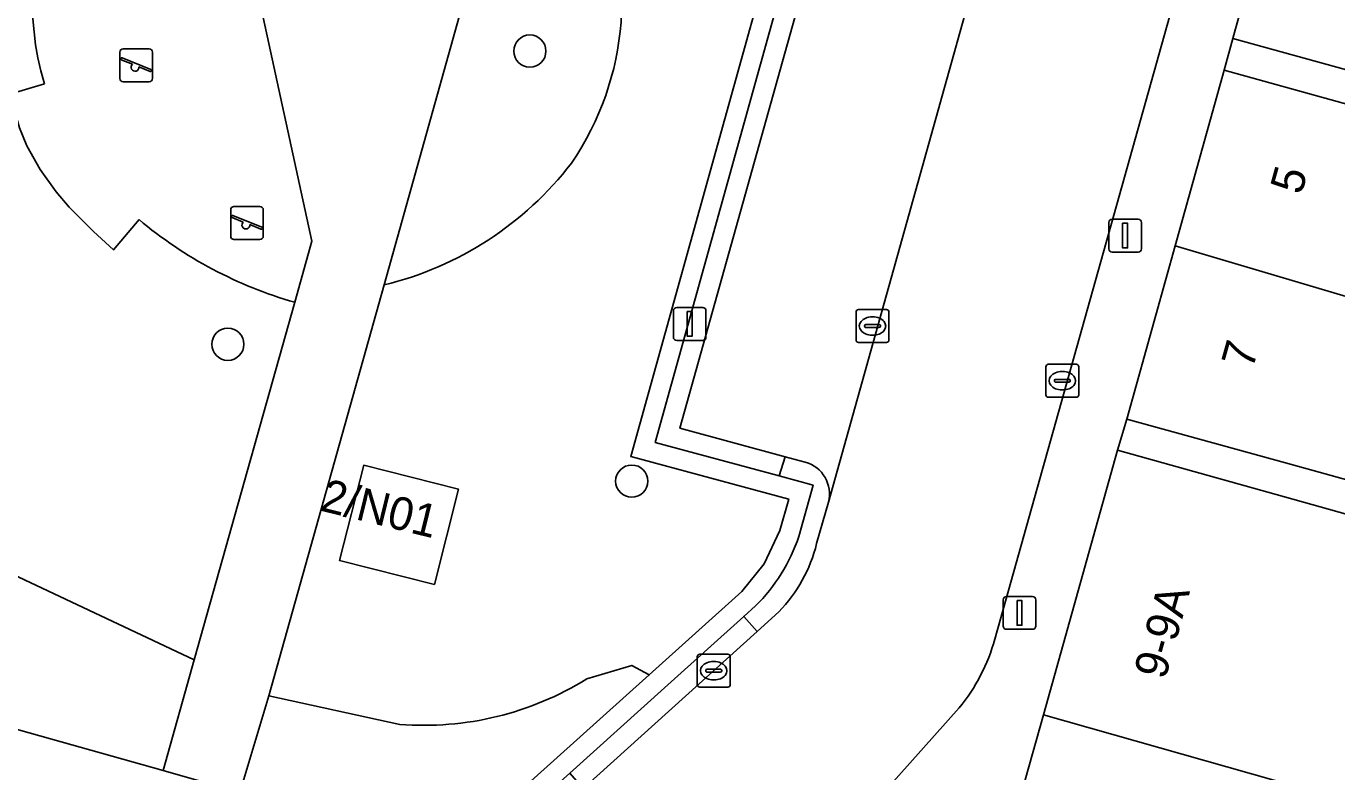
# Model space of a CAD drawing. Extents: x 158086 to 159499, y 382904 to 383981.
# Drawn here: x 158689.97 to 158729.8, y 383283.29 to 383305.96 of the extents above; entities that cross this region are included whole.
import ezdxf

# ---------------------------------------------------------------- set-up
doc = ezdxf.new("R2010")
doc.units = 0
for name, color, linetype in [('IMGEO_Boom', 7, 'Continuous'), ('IMGEO_Erf', 7, 'Continuous'), ('IMGEO_Groenvoorziening', 7, 'Continuous'), ('IMGEO_Haag', 7, 'Continuous'), ('IMGEO_Kolk', 7, 'Continuous'), ('IMGEO_Lichtmast', 7, 'Continuous'), ('IMGEO_Pand', 7, 'Continuous'), ('IMGEO_Pand_nummerreeks', 7, 'Continuous'), ('IMGEO_Parkeervlak_open', 7, 'Continuous'), ('IMGEO_Rijbaan_lokaal_open', 7, 'Continuous'), ('IMGEO_Speelvoorziening', 7, 'Continuous'), ('IMGEO_Terreindeel_zand', 7, 'Continuous'), ('IMGEO_Voetpad_open', 7, 'Continuous')]:
    doc.layers.add(name, color=color, linetype=linetype)

msp = doc.modelspace()

# ---------------------------------------------------------------- linework, layer by layer
at = {"layer": 'IMGEO_Boom'}
for centre in [(158705.278, 383305.204), (158696.102, 383296.29), (158708.374, 383292.129)]:
    msp.add_circle(centre, 0.489, dxfattribs=at)
at = {"layer": 'IMGEO_Erf'}
for points in [[(158750.621, 383298.706), (158746.826, 383299.786), (158746.884, 383299.995), (158740.051, 383301.883), (158726.638, 383305.589), (158726.38, 383304.619), (158731.2, 383303.287), (158735.174, 383302.189), (158737.677, 383301.497), (158736.955, 383298.883), (158739.334, 383298.209), (158739.21, 383297.772), (158742.082, 383296.958), (158741.87, 383296.21), (158745.171, 383295.274), (158744.648, 383293.427), (158746.73, 383292.809), (158748.777, 383292.201), (158750.043, 383296.667)], [(158723.419, 383294.014), (158723.139, 383293.069), (158727.954, 383291.719), (158737.135, 383289.145), (158747.117, 383286.346), (158748.21, 383290.202), (158746.156, 383290.784), (158746.068, 383290.474), (158737.806, 383292.815), (158732.961, 383294.188), (158732.222, 383291.582), (158728.239, 383292.682)]]:
    msp.add_lwpolyline(points, close=True, dxfattribs=at)
at = {"layer": 'IMGEO_Groenvoorziening'}
for points in [[(158715.651, 383319.137), (158708.346, 383292.883), (158713.145, 383291.584), (158712.877, 383290.631), (158712.4, 383289.615), (158711.72, 383288.771), (158708.905, 383286.24), (158705.305, 383283.005), (158704.465, 383281.869), (158703.916, 383280.587), (158704.499, 383280.425), (158704.989, 383281.568), (158705.749, 383282.597), (158706.491, 383283.248), (158709.467, 383285.933)], [(158707.006, 383286.118), (158708.372, 383286.529), (158708.905, 383286.24), (158711.72, 383288.771), (158712.4, 383289.615), (158712.877, 383290.631), (158713.145, 383291.584), (158708.346, 383292.883), (158715.651, 383319.137)], [(158713.449, 383290.447), (158713.886, 383292.005), (158712.858, 383292.286), (158709.086, 383293.304), (158715.763, 383317.299), (158716.138, 383318.648)], [(158707.225, 383310.544), (158703.141, 383306.283), (158700.848, 383298.094)], [(158693.401, 383300.083), (158692.625, 383299.161), (158692.016, 383299.717), (158691.282, 383300.454), (158690.88, 383300.925), (158690.395, 383301.603), (158689.993, 383302.328), (158689.768, 383302.869), (158689.475, 383303.894), (158690.525, 383304.204)], [(158700.848, 383298.094), (158697.345, 383285.602), (158701.326, 383284.735)], [(158687.958, 383290.048), (158695.081, 383286.692), (158698.135, 383297.568)], [(158684.98, 383293.485), (158683.014, 383286.461), (158683.206, 383286.407), (158694.138, 383283.337), (158695.081, 383286.692), (158687.958, 383290.048)], [(158709.467, 383285.933), (158711.776, 383288.016), (158712.136, 383288.337)], [(158701.326, 383284.735), (158697.345, 383285.602), (158696.463, 383282.664), (158703.916, 383280.587), (158704.465, 383281.869), (158705.305, 383283.005), (158708.905, 383286.24), (158708.372, 383286.529), (158707.006, 383286.118)]]:
    msp.add_lwpolyline(points, dxfattribs=at)
msp.add_lwpolyline([(158702.377, 383288.983), (158699.495, 383289.712), (158700.229, 383292.611), (158703.111, 383291.882)], close=True, dxfattribs=at)
for centre, radius, start, end in [((158698.909, 383306.684), 8.744, 114.0649, 196.48), ((158699.264, 383306.766), 8.812, 325.6717, 25.3856), ((158699.264, 383306.766), 8.812, 325.6717, 25.3856), ((158698.436, 383308.029), 10.224, 283.6433, 322.4405), ((158698.436, 383308.029), 10.224, 283.6433, 322.4405), ((158701.631, 383309.861), 12.781, 229.9142, 254.1257), ((158708.419, 383292.113), 5.298, 314.5439, 341.6702), ((158702.056, 383294.094), 9.388, 265.5431, 301.8258), ((158702.056, 383294.094), 9.388, 265.5431, 301.8258)]:
    msp.add_arc(centre, radius, start, end, dxfattribs=at)
at = {"layer": 'IMGEO_Haag'}
for points in [[(158715.651, 383319.137), (158708.346, 383292.883), (158713.145, 383291.584), (158712.877, 383290.631), (158712.4, 383289.615), (158711.72, 383288.771), (158708.905, 383286.24), (158705.305, 383283.005), (158704.465, 383281.869), (158703.916, 383280.587), (158704.499, 383280.425), (158704.989, 383281.568), (158705.749, 383282.597), (158706.491, 383283.248), (158709.467, 383285.933)], [(158713.449, 383290.447), (158713.886, 383292.005), (158712.858, 383292.286), (158709.086, 383293.304), (158715.763, 383317.299), (158716.138, 383318.648)], [(158709.467, 383285.933), (158711.776, 383288.016), (158712.136, 383288.337)]]:
    msp.add_lwpolyline(points, dxfattribs=at)
msp.add_arc((158708.419, 383292.113), 5.298, 314.5439, 341.6702, dxfattribs=at)
at = {"layer": 'IMGEO_Kolk'}
for p, q in [((158715.265, 383297.344), (158716.117, 383297.344)), ((158715.19, 383296.418), (158715.19, 383297.27)), ((158715.678, 383297.124), (158715.703, 383297.124)), ((158716.191, 383297.27), (158716.191, 383296.418)), ((158715.449, 383296.838), (158715.449, 383296.85)), ((158715.887, 383296.801), (158715.489, 383296.801)), ((158715.492, 383296.887), (158715.89, 383296.887)), ((158715.701, 383296.564), (158715.676, 383296.564)), ((158715.933, 383296.85), (158715.933, 383296.838)), ((158716.117, 383296.344), (158715.265, 383296.344)), ((158720.958, 383294.755), (158720.958, 383295.607)), ((158721.033, 383295.681), (158721.885, 383295.681)), ((158721.446, 383295.461), (158721.471, 383295.461)), ((158721.959, 383295.607), (158721.959, 383294.755)), ((158721.217, 383295.175), (158721.217, 383295.187)), ((158721.655, 383295.138), (158721.257, 383295.138)), ((158721.26, 383295.224), (158721.658, 383295.224)), ((158721.701, 383295.187), (158721.701, 383295.175)), ((158721.885, 383294.681), (158721.033, 383294.681)), ((158721.469, 383294.901), (158721.444, 383294.901)), ((158710.365, 383285.94), (158710.365, 383286.792)), ((158710.44, 383286.866), (158711.292, 383286.866)), ((158710.853, 383286.646), (158710.878, 383286.646)), ((158711.366, 383286.792), (158711.366, 383285.94)), ((158710.624, 383286.36), (158710.624, 383286.372)), ((158711.062, 383286.323), (158710.664, 383286.323)), ((158710.667, 383286.409), (158711.065, 383286.409)), ((158711.108, 383286.372), (158711.108, 383286.36)), ((158711.292, 383285.866), (158710.44, 383285.866)), ((158710.876, 383286.086), (158710.851, 383286.086))]:
    msp.add_line(p, q, dxfattribs=at)
for points in [[(158715.265, 383297.344), (158716.117, 383297.344)], [(158715.19, 383296.418), (158715.19, 383297.27)], [(158716.191, 383297.27), (158716.191, 383296.418)], [(158716.117, 383296.344), (158715.265, 383296.344)], [(158720.958, 383294.755), (158720.958, 383295.607)], [(158721.033, 383295.681), (158721.885, 383295.681)], [(158721.959, 383295.607), (158721.959, 383294.755)], [(158721.885, 383294.681), (158721.033, 383294.681)], [(158710.365, 383285.94), (158710.365, 383286.792)], [(158710.44, 383286.866), (158711.292, 383286.866)], [(158711.366, 383286.792), (158711.366, 383285.94)], [(158711.292, 383285.866), (158710.44, 383285.866)]]:
    msp.add_lwpolyline(points, dxfattribs=at)
for centre, radius, start, end in [((158715.267, 383297.268), 0.0765, 91.552, 178.448), ((158715.267, 383297.268), 0.0765, 91.552, 178.448), ((158716.115, 383297.268), 0.0765, 1.552, 88.448), ((158716.115, 383297.268), 0.0765, 1.552, 88.448), ((158715.489, 383296.847), 0.0403, 85.8775, 175.7526), ((158715.486, 383296.837), 0.0366, 178.938, 274.7102), ((158715.89, 383296.844), 0.043, 264.8664, 352.4533), ((158715.894, 383296.849), 0.0386, 1.7309, 96.639), ((158715.267, 383296.42), 0.0765, 181.552, 268.448), ((158715.267, 383296.42), 0.0765, 181.552, 268.448), ((158716.115, 383296.42), 0.0765, 271.552, 358.448), ((158716.115, 383296.42), 0.0765, 271.552, 358.448), ((158721.035, 383295.605), 0.0765, 91.552, 178.448), ((158721.035, 383295.605), 0.0765, 91.552, 178.448), ((158721.883, 383295.605), 0.0765, 1.552, 88.448), ((158721.883, 383295.605), 0.0765, 1.552, 88.448), ((158721.257, 383295.184), 0.0403, 85.8775, 175.7526), ((158721.254, 383295.174), 0.0366, 178.938, 274.7102), ((158721.658, 383295.181), 0.043, 264.8664, 352.4533), ((158721.662, 383295.186), 0.0386, 1.7309, 96.639), ((158721.035, 383294.757), 0.0765, 181.552, 268.448), ((158721.035, 383294.757), 0.0765, 181.552, 268.448), ((158721.883, 383294.757), 0.0765, 271.552, 358.448), ((158721.883, 383294.757), 0.0765, 271.552, 358.448), ((158710.442, 383286.79), 0.0765, 91.552, 178.448), ((158710.442, 383286.79), 0.0765, 91.552, 178.448), ((158711.29, 383286.79), 0.0765, 1.552, 88.448), ((158711.29, 383286.79), 0.0765, 1.552, 88.448), ((158710.664, 383286.369), 0.0403, 85.8775, 175.7526), ((158710.661, 383286.359), 0.0366, 178.938, 274.7102), ((158711.065, 383286.366), 0.043, 264.8664, 352.4533), ((158711.069, 383286.371), 0.0386, 1.7309, 96.639), ((158710.442, 383285.942), 0.0765, 181.552, 268.448), ((158710.442, 383285.942), 0.0765, 181.552, 268.448), ((158711.29, 383285.942), 0.0765, 271.552, 358.448), ((158711.29, 383285.942), 0.0765, 271.552, 358.448)]:
    msp.add_arc(centre, radius, start, end, dxfattribs=at)
for centre, major_axis, ratio, start_param, end_param in [((158715.677, 383296.844), (-0.387, 0.002), 0.722429, 4.712389, 7.853982), ((158715.702, 383296.844), (-0.39, 0.002), 0.717154, 1.570796, 4.712389), ((158721.445, 383295.181), (-0.387, 0.002), 0.722429, 4.712389, 7.853982), ((158721.47, 383295.181), (-0.39, 0.002), 0.717154, 1.570796, 4.712389), ((158710.852, 383286.366), (-0.387, 0.002), 0.722429, 4.712389, 7.853982), ((158710.877, 383286.366), (-0.39, 0.002), 0.717154, 1.570796, 4.712389)]:
    msp.add_ellipse(centre, major_axis=major_axis, ratio=ratio, start_param=start_param, end_param=end_param, dxfattribs=at)
at = {"layer": 'IMGEO_Lichtmast'}
for p, q in [((158722.972, 383300.094), (158723.762, 383300.094)), ((158723.762, 383300.094), (158722.972, 383300.094)), ((158722.872, 383299.194), (158722.872, 383299.994)), ((158722.872, 383299.994), (158722.872, 383299.194)), ((158723.862, 383299.994), (158723.862, 383299.194)), ((158723.862, 383299.194), (158723.862, 383299.994)), ((158723.762, 383299.094), (158722.972, 383299.094)), ((158722.972, 383299.094), (158723.762, 383299.094)), ((158709.64, 383296.507), (158709.64, 383297.307)), ((158709.64, 383297.307), (158709.64, 383296.507)), ((158709.74, 383297.407), (158710.53, 383297.407)), ((158710.53, 383297.407), (158709.74, 383297.407)), ((158710.63, 383297.307), (158710.63, 383296.507)), ((158710.63, 383296.507), (158710.63, 383297.307)), ((158710.53, 383296.407), (158709.74, 383296.407)), ((158709.74, 383296.407), (158710.53, 383296.407)), ((158719.763, 383288.624), (158720.553, 383288.624)), ((158720.553, 383288.624), (158719.763, 383288.624)), ((158719.663, 383287.724), (158719.663, 383288.524)), ((158719.663, 383288.524), (158719.663, 383287.724)), ((158720.653, 383288.524), (158720.653, 383287.724)), ((158720.653, 383287.724), (158720.653, 383288.524)), ((158720.553, 383287.624), (158719.763, 383287.624)), ((158719.763, 383287.624), (158720.553, 383287.624))]:
    msp.add_line(p, q, dxfattribs=at)
for points in [[(158723.292, 383299.969), (158723.442, 383299.969), (158723.442, 383299.219), (158723.292, 383299.219), (158723.292, 383299.969)], [(158710.06, 383297.282), (158710.21, 383297.282), (158710.21, 383296.532), (158710.06, 383296.532), (158710.06, 383297.282)], [(158720.083, 383288.499), (158720.233, 383288.499), (158720.233, 383287.749), (158720.083, 383287.749), (158720.083, 383288.499)]]:
    msp.add_lwpolyline(points, dxfattribs=at)
for centre, start, end in [((158722.972, 383299.994), 90, 180), ((158722.972, 383299.994), 90, 180), ((158723.762, 383299.994), 0, 90), ((158723.762, 383299.994), 360, 90), ((158722.972, 383299.194), 180, 270), ((158722.972, 383299.194), 180, 270), ((158723.762, 383299.194), 270, 0), ((158723.762, 383299.194), 270, 0), ((158709.74, 383297.307), 90, 180), ((158709.74, 383297.307), 90, 180), ((158710.53, 383297.307), 0, 90), ((158710.53, 383297.307), 360, 90), ((158709.74, 383296.507), 180, 270), ((158709.74, 383296.507), 180, 270), ((158710.53, 383296.507), 270, 0), ((158710.53, 383296.507), 270, 0), ((158719.763, 383288.524), 90, 180), ((158719.763, 383288.524), 90, 180), ((158720.553, 383288.524), 0, 90), ((158720.553, 383288.524), 360, 90), ((158719.763, 383287.724), 180, 270), ((158719.763, 383287.724), 180, 270), ((158720.553, 383287.724), 270, 0), ((158720.553, 383287.724), 270, 0)]:
    msp.add_arc(centre, 0.1, start, end, dxfattribs=at)
at = {"layer": 'IMGEO_Pand'}
for points in [[(158734.063, 383310.168), (158729.552, 383311.413), (158728.013, 383310.572), (158726.638, 383305.589), (158740.051, 383301.883), (158746.884, 383299.995), (158746.826, 383299.786), (158750.621, 383298.706), (158752.515, 383305.385), (158748.706, 383306.463), (158747.639, 383302.691), (158742.1, 383304.249), (158743.079, 383307.796), (158742.083, 383309.564), (158738.149, 383310.65), (158736.503, 383309.495), (158734.326, 383310.095)], [(158726.38, 383304.619), (158724.891, 383299.284), (158744.648, 383293.427), (158745.171, 383295.274), (158741.87, 383296.21), (158742.082, 383296.958), (158739.21, 383297.772), (158739.334, 383298.209), (158736.955, 383298.883), (158737.677, 383301.497), (158735.174, 383302.189), (158731.2, 383303.287)], [(158724.891, 383299.284), (158723.419, 383294.014), (158728.239, 383292.682), (158732.222, 383291.582), (158732.961, 383294.188), (158737.806, 383292.815), (158746.068, 383290.474), (158746.156, 383290.784), (158748.21, 383290.202), (158748.777, 383292.201), (158746.73, 383292.809), (158744.648, 383293.427)], [(158747.117, 383286.346), (158737.135, 383289.145), (158727.954, 383291.719), (158723.139, 383293.069), (158720.882, 383285.022), (158729.99, 383282.438), (158730.021, 383282.546), (158734.867, 383281.172), (158742.063, 383279.133), (158745.03, 383278.292), (158745.391, 383279.615), (158745.223, 383279.663)], [(158702.377, 383288.983), (158703.111, 383291.882), (158700.229, 383292.611), (158699.495, 383289.712)], [(158734.867, 383281.172), (158730.021, 383282.546), (158729.99, 383282.438), (158720.882, 383285.022), (158719.351, 383279.567), (158724.166, 383278.217), (158733.304, 383275.655), (158734.145, 383278.623)]]:
    msp.add_lwpolyline(points, close=True, dxfattribs=at)
at = {"layer": 'IMGEO_Parkeervlak_open'}
for points in [[(158720.628, 383315.931), (158716.38, 383317.125), (158709.84, 383293.736), (158713.041, 383292.873), (158713.646, 383292.709)], [(158714.354, 383291.491), (158721.142, 383315.77), (158721.255, 383316.174)]]:
    msp.add_lwpolyline(points, dxfattribs=at)
msp.add_arc((158713.373, 383291.736), 1.011, 345.9856, 74.3516, dxfattribs=at)
at = {"layer": 'IMGEO_Rijbaan_lokaal_open'}
for points in [[(158726.409, 383312.281), (158726.934, 383314.154), (158721.142, 383315.77), (158714.354, 383291.491), (158713.992, 383290.23)], [(158719.408, 383287.329), (158726.409, 383312.281)], [(158712.839, 383288.156), (158712.19, 383287.558), (158706.901, 383282.787), (158706, 383281.923), (158713.492, 383279.816), (158718.325, 383285.237)]]:
    msp.add_lwpolyline(points, dxfattribs=at)
for centre, radius, start, end in [((158709.636, 383291.294), 4.484, 315.5852, 346.2728), ((158713.967, 383288.819), 5.641, 320.5783, 344.6818)]:
    msp.add_arc(centre, radius, start, end, dxfattribs=at)
at = {"layer": 'IMGEO_Speelvoorziening'}
for p, q in [((158692.918, 383305.273), (158693.708, 383305.273)), ((158693.708, 383305.273), (158692.918, 383305.273)), ((158692.818, 383304.373), (158692.818, 383305.173)), ((158692.818, 383305.173), (158692.818, 383304.373)), ((158693.201, 383304.801), (158692.862, 383304.938)), ((158692.887, 383304.998), (158693.763, 383304.645)), ((158693.808, 383305.173), (158693.808, 383304.373)), ((158693.808, 383304.373), (158693.808, 383305.173)), ((158693.739, 383304.585), (158693.399, 383304.722)), ((158693.708, 383304.273), (158692.918, 383304.273)), ((158692.918, 383304.273), (158693.708, 383304.273)), ((158696.187, 383299.578), (158696.187, 383300.378)), ((158696.187, 383300.378), (158696.187, 383299.578)), ((158696.57, 383300.006), (158696.231, 383300.143)), ((158696.256, 383300.203), (158697.132, 383299.85)), ((158696.287, 383300.478), (158697.077, 383300.478)), ((158697.077, 383300.478), (158696.287, 383300.478)), ((158697.177, 383300.378), (158697.177, 383299.578)), ((158697.177, 383299.578), (158697.177, 383300.378)), ((158697.108, 383299.79), (158696.768, 383299.927)), ((158697.077, 383299.478), (158696.287, 383299.478)), ((158696.287, 383299.478), (158697.077, 383299.478))]:
    msp.add_line(p, q, dxfattribs=at)
for centre, radius, start, end in [((158692.918, 383305.173), 0.1, 90, 180), ((158692.918, 383305.173), 0.1, 90, 180), ((158693.708, 383305.173), 0.1, 0, 90), ((158693.708, 383305.173), 0.1, 360, 90), ((158692.875, 383304.968), 0.0327, 68.078, 248.078), ((158693.28, 383304.711), 0.12, 130.9928, 5.1632), ((158693.751, 383304.615), 0.0327, 248.078, 68.078), ((158692.918, 383304.373), 0.1, 180, 270), ((158692.918, 383304.373), 0.1, 180, 270), ((158693.708, 383304.373), 0.1, 270, 0), ((158693.708, 383304.373), 0.1, 270, 0), ((158696.287, 383300.378), 0.1, 90, 180), ((158696.287, 383300.378), 0.1, 90, 180), ((158696.244, 383300.173), 0.0327, 68.078, 248.078), ((158697.077, 383300.378), 0.1, 0, 90), ((158697.077, 383300.378), 0.1, 360, 90), ((158696.649, 383299.916), 0.12, 130.9928, 5.1632), ((158697.12, 383299.82), 0.0327, 248.078, 68.078), ((158696.287, 383299.578), 0.1, 180, 270), ((158696.287, 383299.578), 0.1, 180, 270), ((158697.077, 383299.578), 0.1, 270, 0), ((158697.077, 383299.578), 0.1, 270, 0)]:
    msp.add_arc(centre, radius, start, end, dxfattribs=at)
at = {"layer": 'IMGEO_Terreindeel_zand'}
for points in [[(158698.135, 383297.568), (158698.657, 383299.429), (158695.344, 383314.668)], [(158690.525, 383304.204), (158689.475, 383303.894), (158689.768, 383302.869), (158689.993, 383302.328), (158690.395, 383301.603), (158690.88, 383300.925), (158691.282, 383300.454), (158692.016, 383299.717), (158692.625, 383299.161), (158693.401, 383300.083)]]:
    msp.add_lwpolyline(points, dxfattribs=at)
for centre, radius, start, end in [((158698.909, 383306.684), 8.744, 114.0649, 196.48), ((158701.631, 383309.861), 12.781, 229.9142, 254.1257)]:
    msp.add_arc(centre, radius, start, end, dxfattribs=at)
at = {"layer": 'IMGEO_Voetpad_open'}
for points in [[(158693.404, 383323.589), (158695.344, 383314.668), (158698.657, 383299.429), (158698.135, 383297.568), (158695.081, 383286.692), (158694.138, 383283.337), (158696.463, 383282.664), (158697.345, 383285.602), (158700.848, 383298.094), (158703.141, 383306.283)], [(158712.681, 383278.089), (158705.06, 383280.231), (158704.499, 383280.425), (158703.916, 383280.587), (158696.463, 383282.664), (158694.138, 383283.337), (158683.206, 383286.407), (158683.014, 383286.461), (158682.436, 383286.623), (158684.564, 383294.149), (158692.698, 383323.292)], [(158713.33, 383257.83), (158715.488, 383265.62), (158717.6, 383273.245), (158718.49, 383276.457), (158719.072, 383278.559), (158719.351, 383279.567), (158720.882, 383285.022), (158723.139, 383293.069), (158723.419, 383294.014), (158724.891, 383299.284), (158726.38, 383304.619), (158726.638, 383305.589), (158728.013, 383310.572), (158729.552, 383311.413), (158726.409, 383312.281), (158719.408, 383287.329)], [(158713.646, 383292.709), (158713.041, 383292.873), (158712.858, 383292.286), (158713.886, 383292.005), (158713.449, 383290.447)], [(158713.992, 383290.23), (158714.354, 383291.491)], [(158712.136, 383288.337), (158711.776, 383288.016), (158712.19, 383287.558), (158712.839, 383288.156)], [(158718.325, 383285.237), (158713.492, 383279.816)]]:
    msp.add_lwpolyline(points, dxfattribs=at)
for points in [[(158716.38, 383317.125), (158715.763, 383317.299), (158709.086, 383293.304), (158712.858, 383292.286), (158713.041, 383292.873), (158709.84, 383293.736)], [(158706.491, 383283.248), (158706.901, 383282.787), (158712.19, 383287.558), (158711.776, 383288.016), (158709.467, 383285.933)]]:
    msp.add_lwpolyline(points, close=True, dxfattribs=at)
for centre, radius, start, end in [((158713.373, 383291.736), 1.011, 345.9856, 74.3516), ((158708.419, 383292.113), 5.298, 314.5439, 341.6702), ((158709.636, 383291.294), 4.484, 315.5852, 346.2728), ((158713.967, 383288.819), 5.641, 320.5783, 344.6818)]:
    msp.add_arc(centre, radius, start, end, dxfattribs=at)

# ---------------------------------------------------------------- texts
at = {"layer": 'IMGEO_Pand_nummerreeks'}
for s, rotation, p in [('5', 74.4043, (158728.721, 383300.805)), ('7', 74.3928, (158727.24, 383295.501)), ('2/N01', 346.2005, (158698.868, 383291.242)), ('9-9A', 74.3298, (158724.581, 383286.066))]:
    msp.add_text(s, height=1, rotation=rotation, dxfattribs=at).set_placement(p)

doc.saveas('drawing.dxf')
